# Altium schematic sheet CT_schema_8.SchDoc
size 147 x 119 mm
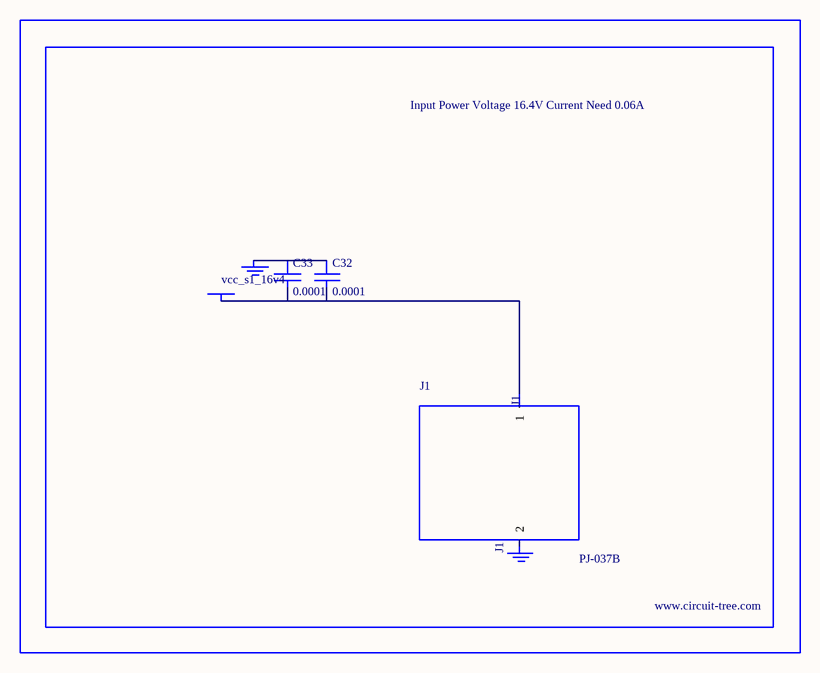
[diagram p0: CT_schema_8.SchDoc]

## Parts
BORDER7  (no value)
C32  0.0001  [EXV-9H]
C33  0.0001  [EXV-9H]
GND_INSTANCE_7_0  (no value)
GND_INSTANCE_7_1  (no value)
J1  PJ-037B  [PJ-037B_PACKAGE]
POWER_INSTANCE_7_0  vcc_s1_16v4

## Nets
NetC32_1: C32.1 C33.1 GND_INSTANCE_7_0.0(GND)
NetC32_2: C32.2 C33.2 J1.1 POWER_INSTANCE_7_0.0(PWR)

Not connected (* = marked no-connect by the designer): GND_INSTANCE_7_1 0(GND); J1 2

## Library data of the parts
BORDER7 = BORDER_PAGE7
C32 C33 = EDK107M035A9HAA
GND_INSTANCE_7_0 GND_INSTANCE_7_1 = GND
POWER_INSTANCE_7_0 = PWR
